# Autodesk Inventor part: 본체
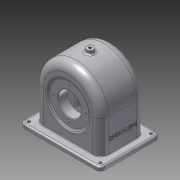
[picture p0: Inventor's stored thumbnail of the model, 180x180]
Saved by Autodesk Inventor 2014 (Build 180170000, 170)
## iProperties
Created: 2016-01
Part Number: 본체
Material: Aluminum 6061
Document SubType Name: Modeling
Designer: user
Density: 2.71 g/cm^3
Appearance: Aluminum - Flat
Mass: 809.753 g
Surface Area: 999.207 cm^2
Volume: 298.802 cm^3
Author: user
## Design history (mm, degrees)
sketch "Sketch1"
  geometry: L1 (-57, -64)-(57, -64); L2 (-57, 0)-(-57, -64); L3 (57, 0)-(57, -64); A1 r 57 centre (0, 0) between (-57, 0) and (57, 0); 2 further points
  constraints: 6 end point, 2 perpendicular, 2 point on circle, 2 tangent, 1 centre point, 1 coincident, 1 horizontal, 1 midpoint, 1 vertical alignment
  dimensions: "d0" = 57 radius of A1; "d1" = 64 distance from line of L1 A1.centre
extrude "Extrusion1" new body sketch "Sketch1" stored distance "d2" = 77; taper "d3" = 0 deg
sketch "Sketch12"
  geometry: L1 (-57, -64)-(-57, 0) reference; L2 (57, 0)-(57, -64) reference; L3 (-51, -64)-(-51, 0); L4 (51, 0)-(51, -64); L5 (57, -64)-(-57, -64) reference; L6 (-51, -64)-(51, -64); A1 r 57 centre (0, 0) between (57, 0) and (-57, 0) reference; A2 r 51 centre (0, 0) between (51, 0) and (-51, 0); 1 further point
  constraints: 6 end point, 2 point on circle, 1 centre point, 1 collinear, 2 other
  dimensions: "d101" = 6 radial gap between concentric circles of A1 A2; "d102" = 64 distance from line of point (0, 0) L6
extrude "Extrusion5" cut sketch "Sketch12" stored distance "d103" = 67; taper "d104" = 0 deg
sketch "Sketch13"
  geometry: L1 (-4, 55.562)-(-4, -74.613); L2 (-64, -33.5)-(-64, 33.5) reference; L3 (-4, -48.5)-(27, -48.5); L4 (0, -33.5)-(51, -33.5) reference; L5 (27, -48.5)-(27, -38.5); L6 (27, -38.5)-(-4, -38.5); L7 (0, -38.5)-(57, -38.5) reference; L8 (-4, 19.5)-(24, 19.5); L9 (0, 33.5)-(0, -33.5) reference; L10 (24, 19.5)-(35.747, 33.5); L11 (33.416, 38.5)-(30.899, 35.5); L12 (30.899, 35.5)-(-4, 35.5); L13 (57, 38.5)-(0, 38.5) reference; L14 (51, 33.5)-(0, 33.5) reference; L15 (35.747, 33.5)-(33.416, 38.5); L16 (33.416, 38.5)-(-4, 38.5); L17 (0, 38.5)-(-64, 38.5) reference; 1 further point
  constraints: 20 end point, 9 point on line, 4 perpendicular, 2 parallel, 1 vertical
  dimensions: "d105" = 60 distance between parallel lines of L1 L2; "d106" = 10 distance of L3.end L5.end; "d107" = 62 diameter of L5 L1; "d108" = 3 distance between parallel lines of L13 L12; "d109" = 56 diameter of L8.end L1; "d110" = 50 deg angle of L8 L10; "d111" = 5 distance between parallel lines of L10 L11; "d112" = 16 distance between parallel lines of L8 L12
revolve "Revolution3" stored, may be unused: angle "d113" = 90 deg
revolve "Revolution4" stored, may be unused: angle "d114" = 90 deg
hole "Hole6" diameter "d117" = 40; stored, may be unused: countersink angle "d121" = 90 deg, drill point angle "d123" = 118 deg; dims "d115" = 10, "d116" = 10, "d118" = 7, "d119" = 4, "d120" = 2, "d122" = 9
sketch "Sketch14" dims "d124" = 48
  geometry: C1 r 37.416 at (0, 0) reference; 3 further points
  constraints: 2 vertical alignment, 1 coincident, 2 other
hole "Hole7" sketch "Sketch14" at (0, 24) diameter "d125" = 2.459; stored, may be unused: countersink angle "d129" = 90 deg, drill point angle "d131" = 118 deg; dims "d126" = 6, "d127" = 4, "d128" = 2, "d130" = 8
sketch "Sketch15" dims "d132" = 56
  geometry: C1 r 20 at (0, 0) reference; C2 r 34.899 at (0, 0) reference; 3 further points
  constraints: 2 vertical alignment, 1 coincident, 2 other
hole "Hole8" sketch "Sketch15" at (0, 28) diameter "d133" = 2.459; stored, may be unused: countersink angle "d137" = 90 deg, drill point angle "d139" = 118 deg; dims "d134" = 7, "d135" = 4, "d136" = 2, "d138" = 9
pattern_circular "Circular Pattern3" dims angle "d141" = 360 deg
sketch "Sketch16"
  geometry: L1 (114, -77)-(114, 0) reference; L2 (0, 0)-(114, 0) reference; L3 (0, 0)-(0, -77) reference; L4 (114, -77)-(0, -77) reference; L5 (-5, 13.5)-(119, 13.5); L6 (127, 5.5)-(127, -82.5); L7 (119, -90.5)-(-5, -90.5); L8 (-13, -82.5)-(-13, 5.5); L9 (-13, 13.5)-(127, -90.5); L10 (127, 13.5)-(-13, -90.5); C1 r 2.5 at (-5, 5.5); C2 r 2.5 at (-5, -82.5); C3 r 2.5 at (119, -82.5); C4 r 2.5 at (119, 5.5); A1 r 8 centre (-5, 5.5) between (-5, 13.5) and (-13, 5.5); A2 r 8 centre (-5, -82.5) between (-13, -82.5) and (-5, -90.5); A3 r 8 centre (119, -82.5) between (119, -90.5) and (127, -82.5); A4 r 8 centre (119, 5.5) between (127, 5.5) and (119, 13.5); 1 further point
  constraints: 12 end point, 8 centre point, 8 point on circle, 8 point on line, 8 tangent, 4 coincident, 3 equal radius, 2 midpoint, 2 parallel, 1 horizontal, 1 perpendicular
  dimensions: "d143" = 140 distance of L9.start L10.start; "d144" = 104 distance of L10.end L9.start; "d145" = 8 radius of A1; "d146" = 5 diameter of C1; "d147" = 5 diameter of C2; "d148" = 5 diameter of C3; "d149" = 5 diameter of C4
extrude "Extrusion6" join sketch "Sketch16" distance "d150" = 7; taper "d151" = 0 deg
workplane "Work Plane2"
sketch "Sketch18"
  geometry: C1 r 6 at (62, 52); 1 further point
  constraints: 1 centre point, 1 coincident
  dimensions: "d154" = 12 diameter of C1
extrude "Extrusion7" join sketch "Sketch18" stored distance "d155" = 7; taper "d156" = 0 deg
hole "Hole9" diameter "d159" = 4.459; stored, may be unused: countersink angle "d163" = 90 deg, drill point angle "d165" = 118 deg; dims "d157" = 10, "d158" = 10, "d160" = 7, "d161" = 4, "d162" = 2, "d164" = 9
fillet "Fillet3" dims "d166" = 9, "d167" = 14, "d168" = 1, "d169" = 3
chamfer "Chamfer3" distance "d170" = 1; stored, may be unused: second distance "d171" = 2, angle "d172" = 45 deg
chamfer "Chamfer4" distance "d173" = 1; stored, may be unused: second distance "d174" = 2, angle "d175" = 45 deg
sketch "Sketch19"
  geometry: L1 (0, 56)-(-49, 56) reference; L2 (-49.387, 25.602)-(0.387, 25.602); L3 (0.387, 25.602)-(0.387, 18.398); L4 (0.387, 18.398)-(-49.387, 18.398); L5 (-49.387, 18.398)-(-49.387, 25.602); L6 (19.5, -8)-(-68.5, -8) reference; 4 further points
  constraints: 3 midpoint, 1 vertical alignment, 2 other
  dimensions: "d176" = 30 distance from line of L6 point (-49.387, 22)
emboss "Emboss2" sketch "Sketch19" dims "d0" = 57, "d1" = 64, "d177" = 0.5, "d178" = 0
body "Solid1"
other parameters: "d152" = -127
